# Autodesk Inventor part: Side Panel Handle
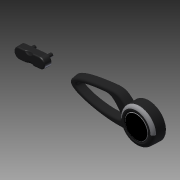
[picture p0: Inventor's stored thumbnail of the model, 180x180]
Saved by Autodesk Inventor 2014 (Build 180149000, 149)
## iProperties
Created: 2009-02
Part Number: Side Panel Handle
Document SubType Name: Modeling
Designer: Autodesk
Density: 1 g/cm^3
Material: Generic
Appearance: Default
Author: Autodesk
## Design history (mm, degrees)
node "side_panel_handle_01_122908.wire"
feature "Sculpt2"
feature "Stitch Surface2"
thicken "Thicken1" dims "d4" = 1
body "Solid2"
feature "Stitch Surface1"
body "Srf2"
body "Srf6"
body "Solid3"
feature "new handle" [Composite]
body "Srf1"
feature "Composite3"
body "Srf5"
